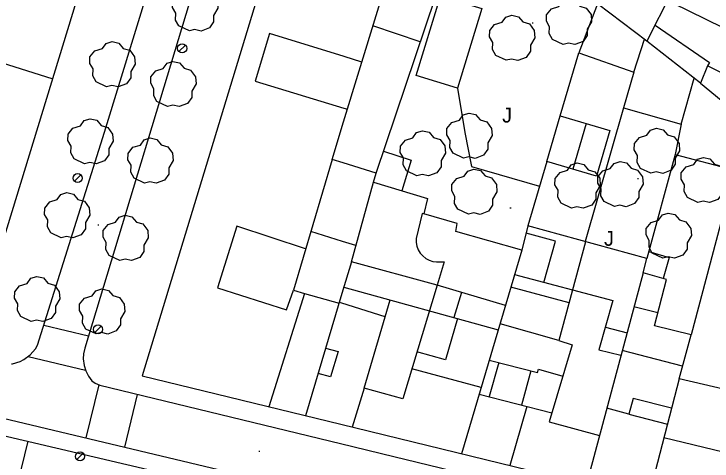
# Model space of a CAD drawing. Extents: x 431390 to 432653, y 4586754 to 4589600.
# Drawn here: x 432092.3 to 432154, y 4587651 to 4587690.5 of the extents above; entities that cross this region are included whole.
import ezdxf

# ---------------------------------------------------------------- set-up
doc = ezdxf.new("R2010")
doc.units = 0
for name, color, linetype in [('COM_17LS_LN', 7, 'Continuous'), ('COM_51_LN', 7, 'Continuous'), ('CON_01_LN', 7, 'Continuous'), ('CON_01FI_LN', 7, 'Continuous'), ('CON_03_LN', 7, 'Continuous'), ('CON_04_LN', 7, 'Continuous'), ('CON_07_LN', 7, 'Continuous'), ('CON_09_LN', 7, 'Continuous'), ('CON_15_LN', 7, 'Continuous'), ('CON_29_LN', 7, 'Continuous'), ('ENE_06_PT', 7, 'Continuous'), ('ORO_03_PT', 7, 'Continuous'), ('TOP_15JA_TX', 7, 'Continuous'), ('VEG_03_PT', 7, 'Continuous'), ('VEG_06_LN', 7, 'Continuous')]:
    doc.layers.add(name, color=color, linetype=linetype)

msp = doc.modelspace()

# ---------------------------------------------------------------- linework, layer by layer
at = {"layer": 'COM_17LS_LN'}
for points in [[(432092.063, 4587659.53), (432092.146, 4587659.541), (432092.826, 4587659.752), (432093.143, 4587659.912), (432093.715, 4587660.335), (432094.179, 4587660.874), (432094.362, 4587661.179), (432100.29, 4587680.016), (432111, 4587714.962), (432115.403, 4587729.599), (432115.334, 4587730.858), (432115.129, 4587731.674), (432114.803, 4587732.45), (432114.363, 4587733.167), (432113.819, 4587733.81), (432098.948, 4587740.984), (432087.838, 4587745.869), (432079.478, 4587749.815), (432077.122, 4587750.796)], [(432119.687, 4587730.821), (432098.538, 4587660.931), (432098.426, 4587660.423), (432098.401, 4587659.992), (432098.468, 4587659.402), (432098.613, 4587658.926), (432098.853, 4587658.45), (432099.152, 4587658.049), (432099.464, 4587657.823), (432099.868, 4587657.646), (432121.129, 4587652.504), (432125.827, 4587651.351), (432157.981, 4587643.532), (432158.106, 4587643.501)], [(432066.476, 4587660.674), (432114.167, 4587649.302), (432121.083, 4587647.603), (432135.943, 4587643.954), (432158.866, 4587638.419)]]:
    msp.add_lwpolyline(points, dxfattribs=at)
at = {"layer": 'COM_51_LN'}
for points in [[(432094.921, 4587662.955), (432098.862, 4587662.003)], [(432093.537, 4587660.203), (432098.596, 4587658.982)], [(432098.664, 4587652.999), (432099.798, 4587657.677)], [(432102.069, 4587652.187), (432103.194, 4587656.842)]]:
    msp.add_lwpolyline(points, dxfattribs=at)
at = {"layer": 'CON_01_LN'}
for points in [[(432021.338, 4587700.513), (432047.183, 4587756.23), (432074.462, 4587750.012), (432092.863, 4587741.826), (432089.971, 4587731.966), (432092.685, 4587729.526), (432096.818, 4587726.785), (432106.854, 4587721.265), (432088.661, 4587661.894), (432069.351, 4587666.555)], [(432139.953, 4587719.486), (432134.506, 4587708.182), (432121.708, 4587714.089), (432120.652, 4587714.577), (432103.59, 4587658.477), (432121.145, 4587654.198), (432142.847, 4587648.908), (432160.558, 4587644.434)], [(432080.515, 4587655.754), (432121.07, 4587646.224)]]:
    msp.add_lwpolyline(points, dxfattribs=at)
at = {"layer": 'CON_01FI_LN'}
for points in [[(432124.038, 4587675.584), (432124.265, 4587676.403), (432121.362, 4587677.306), (432120.384, 4587677.61), (432121.396, 4587680.92), (432127.16, 4587699.762), (432130.789, 4587698.14), (432131.59, 4587699.939), (432132.689, 4587699.337)], [(432150.35, 4587692.325), (432148.2, 4587688.048), (432143.834, 4587691.344), (432142.176, 4587687.013), (432147.047, 4587685.322), (432146.124, 4587682.175), (432151.232, 4587680.722), (432150.692, 4587678.027), (432155.847, 4587676.698)], [(432155.56, 4587684.876), (432153.557, 4587685.861), (432152.918, 4587684.355), (432154.753, 4587682.845), (432155.56, 4587684.876)], [(432139.349, 4587677.416), (432140.537, 4587681.448), (432144.929, 4587680.153), (432143.741, 4587676.121), (432139.349, 4587677.416)], [(432124.038, 4587675.584), (432128.809, 4587674.165), (432128.493, 4587672.788)], [(432156.242, 4587657.004), (432151.04, 4587658.204), (432152.116, 4587662.093), (432148.854, 4587662.911), (432149.924, 4587666.989), (432147.862, 4587667.578), (432148.203, 4587668.84), (432137.678, 4587671.74), (432137.137, 4587669.573), (432131.308, 4587671.241), (432131.432, 4587671.938), (432128.493, 4587672.788)]]:
    msp.add_lwpolyline(points, dxfattribs=at)
at = {"layer": 'CON_03_LN'}
for points in [[(432095.662, 4587684.74), (432086.209, 4587687.707)], [(432122.091, 4587668.546), (432124.038, 4587675.584)], [(432128.493, 4587672.788), (432128.349, 4587672.83), (432127.804, 4587670.617), (432127.806, 4587670.276), (432127.869, 4587669.941), (432127.991, 4587669.622), (432128.166, 4587669.33), (432128.39, 4587669.074), (432128.657, 4587668.861), (432128.956, 4587668.699), (432129.28, 4587668.592), (432129.617, 4587668.544), (432130.29, 4587668.561), (432129.678, 4587666.489)], [(432137.137, 4587669.573), (432131.831, 4587651.593)], [(432122.091, 4587668.546), (432121.254, 4587665.749), (432118.023, 4587654.959)], [(432147.862, 4587667.578), (432142.847, 4587648.908)], [(432129.678, 4587666.489), (432126.624, 4587656.447), (432123.217, 4587657.391), (432122.151, 4587653.953)], [(432151.04, 4587658.204), (432148.282, 4587647.535)], [(432093.517, 4587652.699), (432091.463, 4587644.375), (432091.104, 4587642.919)]]:
    msp.add_lwpolyline(points, dxfattribs=at)
at = {"layer": 'CON_04_LN'}
for points in [[(432150.443, 4587692.664), (432150.986, 4587692.373), (432150.455, 4587691.429), (432156.349, 4587688.559), (432156.806, 4587689.553), (432157.564, 4587689.212)], [(432148.914, 4587689.468), (432153.735, 4587686.157), (432153.557, 4587685.861)], [(432123.015, 4587686.211), (432121.451, 4587686.696), (432114.858, 4587688.738), (432113.598, 4587684.505), (432121.408, 4587682.134), (432121.737, 4587682.034)], [(432147.047, 4587685.322), (432147.973, 4587688.219)], [(432152.918, 4587684.355), (432148.2, 4587688.048)], [(432151.232, 4587680.722), (432152.381, 4587684.775)], [(432120.384, 4587677.61), (432116.96, 4587666.046), (432117.934, 4587665.744), (432114.806, 4587655.743)], [(432118.044, 4587669.708), (432111.975, 4587671.7), (432110.253, 4587666.263), (432116.359, 4587664.311), (432116.96, 4587666.046)], [(432122.49, 4587669.987), (432121.297, 4587670.358), (432118.495, 4587671.23)], [(432139.085, 4587666.738), (432140.118, 4587670.389), (432137.516, 4587671.09)], [(432142.778, 4587670.335), (432140.423, 4587661.609), (432141.597, 4587661.222), (432139.566, 4587654.424), (432143.999, 4587653.197)], [(432129.678, 4587666.489), (432122.091, 4587668.546)], [(432136.502, 4587667.422), (432145.181, 4587665.124), (432143.96, 4587660.791), (432145.905, 4587660.294)], [(432121.424, 4587666.316), (432135.064, 4587662.547)], [(432135.696, 4587664.69), (432129.678, 4587666.489)], [(432141.322, 4587664.938), (432136.174, 4587666.309)], [(432117.934, 4587665.744), (432121, 4587664.902)], [(432131.804, 4587665.853), (432131.146, 4587663.63)], [(432125.067, 4587663.699), (432121.246, 4587664.89), (432121.018, 4587664.961)], [(432123.217, 4587657.391), (432125.504, 4587665.188)], [(432149.15, 4587664.039), (432147.055, 4587664.574)], [(432131.449, 4587663.546), (432130.418, 4587659.889), (432127.885, 4587660.595)], [(432144.525, 4587662.795), (432146.439, 4587662.28)], [(432119.809, 4587660.923), (432120.932, 4587660.63), (432120.237, 4587658.383), (432119.14, 4587658.691)], [(432151.352, 4587659.33), (432146.017, 4587660.711)], [(432134.274, 4587659.87), (432138.52, 4587658.775), (432138.634, 4587659.079), (432140.769, 4587658.45)], [(432135.115, 4587659.653), (432134.271, 4587656.64)], [(432133.561, 4587657.455), (432127.432, 4587659.103)], [(432137.941, 4587658.924), (432137.127, 4587655.895)], [(432133.388, 4587656.87), (432139.797, 4587655.198)], [(432150.373, 4587655.624), (432146.99, 4587656.467), (432146.607, 4587655.083), (432150.01, 4587654.218)], [(432137.589, 4587655.774), (432136.081, 4587650.557)]]:
    msp.add_lwpolyline(points, dxfattribs=at)
at = {"layer": 'CON_07_LN'}
for points in [[(432124.917, 4587678.337), (432127.359, 4587677.548), (432126.532, 4587674.842)], [(432148.37, 4587669.455), (432150.177, 4587668.943), (432149.642, 4587667.07)]]:
    msp.add_lwpolyline(points, dxfattribs=at)
at = {"layer": 'CON_09_LN'}
msp.add_lwpolyline([(432127.809, 4587685.011), (432129.966, 4587692.059), (432133.628, 4587690.938), (432131.471, 4587683.89), (432127.809, 4587685.011)], dxfattribs=at)
at = {"layer": 'CON_15_LN'}
for points in [[(432124.265, 4587676.403), (432132.103, 4587699.658)], [(432128.172, 4587687.996), (432123.997, 4587689.423)], [(432140.537, 4587681.448), (432142.176, 4587687.013)], [(432146.124, 4587682.175), (432142.753, 4587670.342)], [(432150.692, 4587678.027), (432148.203, 4587668.84)], [(432139.349, 4587677.416), (432137.678, 4587671.74)], [(432155.606, 4587675.328), (432152.116, 4587662.093)]]:
    msp.add_lwpolyline(points, dxfattribs=at)
at = {"layer": 'CON_29_LN'}
for points in [[(432142.836, 4587680.77), (432141.661, 4587676.734)], [(432140.423, 4587661.609), (432135.219, 4587663.073)], [(432146.607, 4587655.083), (432144.647, 4587655.609)], [(432154.931, 4587651.746), (432149.698, 4587653.011)]]:
    msp.add_lwpolyline(points, dxfattribs=at)
at = {"layer": 'ENE_06_PT'}
for p, q in [((432107.421, 4587687.702), (432106.855, 4587687.136)), ((432098.196, 4587676.236), (432097.63, 4587675.67)), ((432099.993, 4587662.872), (432099.427, 4587662.306)), ((432098.396, 4587651.638), (432097.83, 4587651.072))]:
    msp.add_line(p, q, dxfattribs=at)
for centre in [(432107.138, 4587687.419), (432097.913, 4587675.953), (432099.71, 4587662.589), (432098.113, 4587651.355)]:
    msp.add_circle(centre, 0.4, dxfattribs=at)
at = {"layer": 'ORO_03_PT'}
for p, q in [((432138.054, 4587689.682), (432138.154, 4587689.682)), ((432147.366, 4587675.928), (432147.466, 4587675.928)), ((432136.093, 4587673.332), (432136.193, 4587673.332)), ((432099.682, 4587671.829), (432099.782, 4587671.829)), ((432113.899, 4587651.826), (432113.999, 4587651.826))]:
    msp.add_line(p, q, dxfattribs=at)
at = {"layer": 'VEG_03_PT'}
for points in [[(432107.772, 4587688.967), (432106.845, 4587689.402), (432106.557, 4587689.923), (432106.58, 4587690.537), (432106.298, 4587691.029), (432106.306, 4587691.592), (432106.747, 4587692.127), (432107.4, 4587692.331), (432107.735, 4587692.782), (432108.261, 4587692.952), (432108.841, 4587692.819), (432109.241, 4587692.353), (432109.815, 4587692.183), (432110.249, 4587691.6), (432110.298, 4587690.958), (432109.915, 4587690.311), (432109.915, 4587689.761), (432109.543, 4587689.227), (432108.804, 4587688.952), (432108.239, 4587689.08), (432107.772, 4587688.967)], [(432140.791, 4587687.765), (432139.864, 4587688.2), (432139.576, 4587688.721), (432139.599, 4587689.335), (432139.317, 4587689.827), (432139.325, 4587690.39), (432139.766, 4587690.925), (432140.419, 4587691.129), (432140.754, 4587691.58), (432141.28, 4587691.75), (432141.86, 4587691.617), (432142.26, 4587691.151), (432142.834, 4587690.981), (432143.268, 4587690.398), (432143.317, 4587689.756), (432142.934, 4587689.109), (432142.934, 4587688.559), (432142.562, 4587688.025), (432141.823, 4587687.75), (432141.258, 4587687.878), (432140.791, 4587687.765)], [(432135.772, 4587686.365), (432134.845, 4587686.8), (432134.557, 4587687.321), (432134.58, 4587687.935), (432134.298, 4587688.427), (432134.306, 4587688.99), (432134.747, 4587689.525), (432135.4, 4587689.729), (432135.735, 4587690.18), (432136.261, 4587690.35), (432136.841, 4587690.217), (432137.241, 4587689.751), (432137.815, 4587689.581), (432138.249, 4587688.998), (432138.298, 4587688.356), (432137.915, 4587687.709), (432137.915, 4587687.159), (432137.543, 4587686.625), (432136.804, 4587686.35), (432136.239, 4587686.478), (432135.772, 4587686.365)], [(432100.46, 4587684.033), (432099.533, 4587684.468), (432099.245, 4587684.989), (432099.268, 4587685.603), (432098.986, 4587686.095), (432098.994, 4587686.658), (432099.435, 4587687.193), (432100.088, 4587687.397), (432100.423, 4587687.848), (432100.949, 4587688.018), (432101.529, 4587687.885), (432101.929, 4587687.419), (432102.503, 4587687.249), (432102.937, 4587686.666), (432102.986, 4587686.024), (432102.603, 4587685.377), (432102.603, 4587684.827), (432102.231, 4587684.293), (432101.492, 4587684.018), (432100.927, 4587684.146), (432100.46, 4587684.033)], [(432105.839, 4587682.282), (432104.912, 4587682.717), (432104.624, 4587683.238), (432104.647, 4587683.852), (432104.365, 4587684.344), (432104.373, 4587684.907), (432104.814, 4587685.442), (432105.467, 4587685.646), (432105.802, 4587686.097), (432106.328, 4587686.267), (432106.908, 4587686.134), (432107.308, 4587685.668), (432107.882, 4587685.498), (432108.316, 4587684.915), (432108.365, 4587684.273), (432107.982, 4587683.626), (432107.982, 4587683.076), (432107.61, 4587682.542), (432106.871, 4587682.267), (432106.306, 4587682.395), (432105.839, 4587682.282)], [(432131.998, 4587677.715), (432131.071, 4587678.15), (432130.783, 4587678.671), (432130.806, 4587679.285), (432130.524, 4587679.777), (432130.532, 4587680.34), (432130.973, 4587680.875), (432131.626, 4587681.079), (432131.961, 4587681.53), (432132.487, 4587681.7), (432133.067, 4587681.567), (432133.467, 4587681.101), (432134.041, 4587680.931), (432134.475, 4587680.348), (432134.524, 4587679.706), (432134.141, 4587679.059), (432134.141, 4587678.509), (432133.769, 4587677.975), (432133.03, 4587677.7), (432132.465, 4587677.828), (432131.998, 4587677.715)], [(432098.518, 4587677.216), (432097.591, 4587677.651), (432097.303, 4587678.172), (432097.326, 4587678.786), (432097.044, 4587679.278), (432097.052, 4587679.841), (432097.493, 4587680.376), (432098.146, 4587680.58), (432098.481, 4587681.031), (432099.007, 4587681.201), (432099.587, 4587681.068), (432099.987, 4587680.602), (432100.561, 4587680.432), (432100.995, 4587679.849), (432101.044, 4587679.207), (432100.661, 4587678.56), (432100.661, 4587678.01), (432100.289, 4587677.476), (432099.55, 4587677.201), (432098.985, 4587677.329), (432098.518, 4587677.216)], [(432148.559, 4587676.381), (432147.632, 4587676.816), (432147.344, 4587677.337), (432147.367, 4587677.951), (432147.085, 4587678.443), (432147.093, 4587679.006), (432147.534, 4587679.541), (432148.187, 4587679.745), (432148.522, 4587680.196), (432149.048, 4587680.366), (432149.628, 4587680.233), (432150.028, 4587679.767), (432150.602, 4587679.597), (432151.036, 4587679.014), (432151.085, 4587678.372), (432150.702, 4587677.725), (432150.702, 4587677.175), (432150.33, 4587676.641), (432149.591, 4587676.366), (432149.026, 4587676.494), (432148.559, 4587676.381)], [(432127.881, 4587676.16), (432126.954, 4587676.595), (432126.666, 4587677.116), (432126.689, 4587677.73), (432126.407, 4587678.222), (432126.415, 4587678.785), (432126.856, 4587679.32), (432127.509, 4587679.524), (432127.844, 4587679.975), (432128.37, 4587680.145), (432128.95, 4587680.012), (432129.35, 4587679.546), (432129.924, 4587679.376), (432130.358, 4587678.793), (432130.407, 4587678.151), (432130.024, 4587677.504), (432130.024, 4587676.954), (432129.652, 4587676.42), (432128.913, 4587676.145), (432128.348, 4587676.273), (432127.881, 4587676.16)], [(432103.819, 4587675.514), (432102.892, 4587675.949), (432102.604, 4587676.47), (432102.627, 4587677.084), (432102.345, 4587677.576), (432102.353, 4587678.139), (432102.794, 4587678.674), (432103.447, 4587678.878), (432103.782, 4587679.329), (432104.308, 4587679.499), (432104.888, 4587679.366), (432105.288, 4587678.9), (432105.862, 4587678.73), (432106.296, 4587678.147), (432106.345, 4587677.505), (432105.962, 4587676.858), (432105.962, 4587676.308), (432105.59, 4587675.774), (432104.851, 4587675.499), (432104.286, 4587675.627), (432103.819, 4587675.514)], [(432152.701, 4587673.803), (432151.774, 4587674.238), (432151.486, 4587674.759), (432151.509, 4587675.373), (432151.227, 4587675.865), (432151.235, 4587676.428), (432151.676, 4587676.963), (432152.329, 4587677.167), (432152.664, 4587677.618), (432153.19, 4587677.788), (432153.77, 4587677.655), (432154.17, 4587677.189), (432154.744, 4587677.019), (432155.178, 4587676.436), (432155.227, 4587675.794), (432154.844, 4587675.147), (432154.844, 4587674.597), (432154.472, 4587674.063), (432153.733, 4587673.788), (432153.168, 4587673.916), (432152.701, 4587673.803)], [(432141.549, 4587673.303), (432140.622, 4587673.738), (432140.334, 4587674.259), (432140.357, 4587674.873), (432140.075, 4587675.365), (432140.083, 4587675.928), (432140.524, 4587676.463), (432141.177, 4587676.667), (432141.512, 4587677.118), (432142.038, 4587677.288), (432142.618, 4587677.155), (432143.018, 4587676.689), (432143.592, 4587676.519), (432144.026, 4587675.936), (432144.075, 4587675.294), (432143.692, 4587674.647), (432143.692, 4587674.097), (432143.32, 4587673.563), (432142.581, 4587673.288), (432142.016, 4587673.416), (432141.549, 4587673.303)], [(432145.334, 4587673.438), (432144.407, 4587673.873), (432144.119, 4587674.394), (432144.142, 4587675.008), (432143.86, 4587675.5), (432143.868, 4587676.063), (432144.309, 4587676.598), (432144.962, 4587676.802), (432145.297, 4587677.253), (432145.823, 4587677.423), (432146.403, 4587677.29), (432146.803, 4587676.824), (432147.377, 4587676.654), (432147.811, 4587676.071), (432147.86, 4587675.429), (432147.477, 4587674.782), (432147.477, 4587674.232), (432147.105, 4587673.698), (432146.366, 4587673.423), (432145.801, 4587673.551), (432145.334, 4587673.438)], [(432132.426, 4587672.76), (432131.499, 4587673.195), (432131.211, 4587673.716), (432131.234, 4587674.33), (432130.952, 4587674.822), (432130.96, 4587675.385), (432131.401, 4587675.92), (432132.054, 4587676.124), (432132.389, 4587676.575), (432132.915, 4587676.745), (432133.495, 4587676.612), (432133.895, 4587676.146), (432134.469, 4587675.976), (432134.903, 4587675.393), (432134.952, 4587674.751), (432134.569, 4587674.104), (432134.569, 4587673.554), (432134.197, 4587673.02), (432133.458, 4587672.745), (432132.893, 4587672.873), (432132.426, 4587672.76)], [(432096.458, 4587670.685), (432095.531, 4587671.12), (432095.243, 4587671.641), (432095.266, 4587672.255), (432094.984, 4587672.747), (432094.992, 4587673.31), (432095.433, 4587673.845), (432096.086, 4587674.049), (432096.421, 4587674.5), (432096.947, 4587674.67), (432097.527, 4587674.537), (432097.927, 4587674.071), (432098.501, 4587673.901), (432098.935, 4587673.318), (432098.984, 4587672.676), (432098.601, 4587672.029), (432098.601, 4587671.479), (432098.229, 4587670.945), (432097.49, 4587670.67), (432096.925, 4587670.798), (432096.458, 4587670.685)], [(432149.599, 4587668.88), (432148.672, 4587669.315), (432148.384, 4587669.836), (432148.407, 4587670.45), (432148.125, 4587670.942), (432148.133, 4587671.505), (432148.574, 4587672.04), (432149.227, 4587672.244), (432149.562, 4587672.695), (432150.088, 4587672.865), (432150.668, 4587672.732), (432151.068, 4587672.266), (432151.642, 4587672.096), (432152.076, 4587671.513), (432152.125, 4587670.871), (432151.742, 4587670.224), (432151.742, 4587669.674), (432151.37, 4587669.14), (432150.631, 4587668.865), (432150.066, 4587668.993), (432149.599, 4587668.88)], [(432101.622, 4587668.685), (432100.695, 4587669.12), (432100.407, 4587669.641), (432100.43, 4587670.255), (432100.148, 4587670.747), (432100.156, 4587671.31), (432100.597, 4587671.845), (432101.25, 4587672.049), (432101.585, 4587672.5), (432102.111, 4587672.67), (432102.691, 4587672.537), (432103.091, 4587672.071), (432103.665, 4587671.901), (432104.099, 4587671.318), (432104.148, 4587670.676), (432103.765, 4587670.029), (432103.765, 4587669.479), (432103.393, 4587668.945), (432102.654, 4587668.67), (432102.089, 4587668.798), (432101.622, 4587668.685)], [(432093.806, 4587663.284), (432092.879, 4587663.719), (432092.591, 4587664.24), (432092.614, 4587664.854), (432092.332, 4587665.346), (432092.34, 4587665.909), (432092.781, 4587666.444), (432093.434, 4587666.648), (432093.769, 4587667.099), (432094.295, 4587667.269), (432094.875, 4587667.136), (432095.275, 4587666.67), (432095.849, 4587666.5), (432096.283, 4587665.917), (432096.332, 4587665.275), (432095.949, 4587664.628), (432095.949, 4587664.078), (432095.577, 4587663.544), (432094.838, 4587663.269), (432094.273, 4587663.397), (432093.806, 4587663.284)], [(432099.547, 4587662.183), (432098.62, 4587662.618), (432098.332, 4587663.139), (432098.355, 4587663.753), (432098.073, 4587664.245), (432098.081, 4587664.808), (432098.522, 4587665.343), (432099.175, 4587665.547), (432099.51, 4587665.998), (432100.036, 4587666.168), (432100.616, 4587666.035), (432101.016, 4587665.569), (432101.59, 4587665.399), (432102.024, 4587664.816), (432102.073, 4587664.174), (432101.69, 4587663.527), (432101.69, 4587662.977), (432101.318, 4587662.443), (432100.579, 4587662.168), (432100.014, 4587662.296), (432099.547, 4587662.183)]]:
    msp.add_lwpolyline(points, dxfattribs=at)
at = {"layer": 'VEG_06_LN'}
msp.add_lwpolyline([(432131.471, 4587683.89), (432132.115, 4587679.986), (432132.704, 4587676.971), (432138.711, 4587675.248)], dxfattribs=at)

# ---------------------------------------------------------------- texts
at = {"layer": 'TOP_15JA_TX'}
for p in [(432135.409, 4587680.865), (432144.412, 4587669.971)]:
    msp.add_text('J', height=1.3, dxfattribs=at).set_placement(p)

doc.saveas('drawing.dxf')
